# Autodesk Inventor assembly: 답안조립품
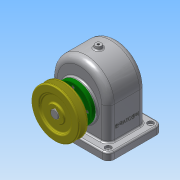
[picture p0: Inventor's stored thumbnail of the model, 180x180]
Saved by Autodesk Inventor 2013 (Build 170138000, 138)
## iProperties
Created: 2016-10
Part Number: 답안조립품
Document SubType Name: Assembly
Designer: Administrator
Author: Administrator
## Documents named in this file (15)
- C:\Users\Administrator\Desktop\461008V1020\답안조립품.iam
- C:\Users\Administrator\Desktop\461008V1020\본체.ipt
- C:\Users\Administrator\Desktop\461008V1020\축.ipt
- C:\Users\Administrator\Desktop\461008V1020\앞커버.ipt
- C:\Users\Administrator\Desktop\461008V1020\뒤커버.ipt
- C:\Users\Administrator\Desktop\461008V1020\볼트 M3 x 10.ipt
- C:\Users\Administrator\Desktop\461008V1020\볼트 M3 x 8.ipt
- C:\Users\Administrator\Desktop\461008V1020\베어링 6203.ipt
- C:\Users\Administrator\Desktop\461008V1020\스퍼기어.ipt
- C:\Users\Administrator\Desktop\461008V1020\키 - 6 x 6 x 22.ipt
- C:\Users\Administrator\Desktop\461008V1020\오일씰 28 40 8.ipt
- C:\Users\Administrator\Desktop\461008V1020\키 - 5 x 5 x 18.ipt
- C:\Users\Administrator\Desktop\461008V1020\부시.ipt
- C:\Users\Administrator\Desktop\461008V1020\V-벨트풀리.ipt
- C:\Users\Administrator\Desktop\461008V1020\멈춤나사 - M4x10.ipt
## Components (9 placed, 3 different names)
1. V-벨트풀리:1 — 각도:4
2. ISO 4762 M3 x 10:1
3. ISO 4762 M3 x 10:2
4. ISO 4762 M3 x 10:3
5. ISO 4762 M3 x 10:4
6. ISO 4762 M3 x 8:1
7. ISO 4762 M3 x 8:2
8. ISO 4762 M3 x 8:3
9. ISO 4762 M3 x 8:4
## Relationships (1: Angle 1)
- 각도:4 [Angle]: V-벨트풀리:1
